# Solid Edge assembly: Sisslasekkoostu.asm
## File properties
Author: Türk
Template: Iso Assembly.asm
Last saved by: Türk
Revision: 3
Application: Solid Edge
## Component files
Sisselase.par
Sisselasekeklappkoostu.asm
s.par
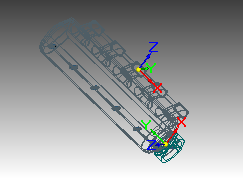
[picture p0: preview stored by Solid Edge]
